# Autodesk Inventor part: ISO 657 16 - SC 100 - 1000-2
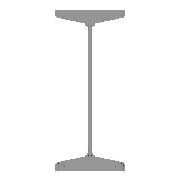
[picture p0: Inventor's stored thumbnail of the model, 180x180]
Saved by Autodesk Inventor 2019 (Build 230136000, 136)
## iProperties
_CCFamilyMember: 1
_CCFamilyDisplayName: ISO 657/16 - 1980 - Poutres en acier laminées à chaud - Partie 16: profilés en H (série métrique) - Cotes et propriétés de section
_FrameMemberDoc: Frame Member File
_Version: 15.0.0
_GetPNFromCC: 1
Created: 2018-07
Part Number: ISO 657 16 - SC 100 - 1000-2
Material: Acier, doux
Description: Poutres en acier laminées à chaud - Partie 16: profilés en H (série métrique) - Cotes et propriétés de section
Document SubType Name: Modeling
Standard: ISO
Designer: Fabian Perrée
Standard Revision: First edition 1980-02-15
Standards Organization: ISO
Language: fr-FR
Size Designation: SC 100
Categories: <MemberInstance><Categories><Category DisplayName="Profilés" InternalName="089c4875-fa83-4c05-b084-43b9cc11f5ed" Mnemonic="GRDR"><CategoryParameter DisplayName=
Stock Number: SC 100
Density: 7.85 g/cm^3
Appearance: Semi-poli
Mass: 19656.9 g
Surface Area: 5357.79 cm^2
Volume: 2504.06 cm^3
IsCustomPart: 1
G_W: 100,000 mm
G_H: 100,000 mm
+66B73B83-1ABF-4F18-8224-AF9602477DE0+DETAILDECOUPE1: Grugeage
+9F30C4B5-7857-4BA6-ACFD-6D0F8F96A7E8+DETAILDECOUPE2: Grugeage
G_L: 1000,000 mm
Author: Fabian Perrée
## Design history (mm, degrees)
node "Plan de départ"
node "Plan de fin"
sketch "Esquisse"
  geometry: L1 (-3, 0)-(-3, -26.266); L2 (-13.33, -38.149)-(-44.835, -42.577); L3 (-50, -48.518)-(-50, -50); L4 (-50, -50)-(0, -50); L5 (-26.5, -50)-(-26.5, -40); L6 (-61.333, 0)-(81.777, 0); L7 (0, 0)-(0, -50); L8 (0, -60)-(0, 80); L9 (3, 0)-(3, -26.266); L10 (13.33, -38.149)-(44.835, -42.577); L11 (50, -48.518)-(50, -50); L12 (50, -50)-(0, -50); L13 (-3, 0)-(0, 0); L14 (-3, 0)-(-3, 26.266); L15 (-13.33, 38.149)-(-44.835, 42.577); L16 (-50, 48.518)-(-50, 50); L17 (-50, 50)-(0, 50); L18 (50, 48.518)-(50, 50); L19 (13.33, 38.149)-(44.835, 42.577); L20 (3, 0)-(3, 26.266); L21 (50, 50)-(0, 50); L22 (0, 108)-(0, -88) reference; L23 (-89.955, 0)-(110.399, 0) reference; A1 r 6 centre (-44, 48.518) between (-50, 48.518) and (-44.835, 42.577); A2 r 6 centre (44, 48.518) between (44.835, 42.577) and (50, 48.518); A3 r 6 centre (44, -48.518) between (50, -48.518) and (44.835, -42.577); A4 r 6 centre (-44, -48.518) between (-44.835, -42.577) and (-50, -48.518); A5 r 12 centre (-15, 26.266) between (-3, 26.266) and (-13.33, 38.149); A6 r 12 centre (15, 26.266) between (13.33, 38.149) and (3, 26.266); A7 r 12 centre (15, -26.266) between (3, -26.266) and (13.33, -38.149); A8 r 12 centre (-15, -26.266) between (-13.33, -38.149) and (-3, -26.266); 14 further points
  constraints: 42 end point, 24 point on line, 17 symmetric about line, 16 point on circle, 16 tangent, 8 centre point, 6 equal radius, 4 collinear, 2 perpendicular, 12 other
  dimensions: "d1" = 10 vertical distance of L3.end L5.end (= G_T1); "d2" = 23.5 distance between parallel lines of L5 L3 (= -0.25 x G_T + 0.25 x G_W); "d3" = 3 distance between parallel lines of L1 L7 (= 0.5 x G_T); "d4" = 50 distance between parallel lines of L7 L3 (= 0.5 x G_W); "d9" = 50 distance from line of L1.start L4 (= 0.5 x G_H); "d14" = 98 deg angle of L2 L1 (= G_NG); "d15" = 6 radius of A1 (= G_ER); "d16" = 12 radius of A5 (= G_IR)
extrude "Corps" new body sketch "Esquisse" stored distance "d5" = 1000 (= G_L); taper "d6" = 0 deg
node "Driven Length"
  sketch "Sketch3"
    geometry: L1 (0, 0)-(10, 0) reference
    constraints: 2 end point, 1 horizontal
  workplane "Work Plane3"
  sketch "Sketch4"
    geometry: L1 (-2, 0)-(12, 0) reference; L2 (-2, 1000)-(12, 1000) reference
    dimensions: "d20" = 1000 distance between parallel lines of L1 L2 (derived)
node "Plan de construction4"
node "Plan de construction5"
node "Plan de construction6"
sketch "Esquisse5"
  geometry: L1 (-3, 0)-(-3, -26.266); L2 (-13.33, -38.149)-(-44.835, -42.577); L3 (-50, -48.518)-(-50, -50); L4 (-50, -50)-(0, -50); L5 (50, -50)-(0, -50); L6 (50, -48.518)-(50, -50); L7 (13.33, -38.149)-(44.835, -42.577); L8 (3, 0)-(3, -26.266); L9 (3, 0)-(3, 26.266); L10 (13.33, 38.149)-(44.835, 42.577); L11 (50, 48.518)-(50, 50); L12 (50, 50)-(0, 50); L13 (-50, 50)-(0, 50); L14 (-50, 48.518)-(-50, 50); L15 (-13.33, 38.149)-(-44.835, 42.577); L16 (-3, 0)-(-3, 26.266); A1 r 12 centre (-15, -26.266) between (-13.33, -38.149) and (-3, -26.266); A2 r 6 centre (-44, -48.518) between (-44.835, -42.577) and (-50, -48.518); A3 r 6 centre (44, -48.518) between (50, -48.518) and (44.835, -42.577); A4 r 12 centre (15, -26.266) between (3, -26.266) and (13.33, -38.149); A5 r 12 centre (15, 26.266) between (13.33, 38.149) and (3, 26.266); A6 r 6 centre (44, 48.518) between (44.835, 42.577) and (50, 48.518); A7 r 6 centre (-44, 48.518) between (-50, 48.518) and (-44.835, 42.577); A8 r 12 centre (-15, 26.266) between (-3, 26.266) and (-13.33, 38.149)
  constraints: 32 end point, 16 point on circle, 8 centre point
extrude "Extrusion2" cut sketch "Esquisse5" stored distance "d21" = 0.13; taper "d22" = 0 deg
node "Plan de construction7"
node "Plan de construction8"
node "Plan de construction9"
sketch "Esquisse6"
  geometry: L1 (-3, 0)-(-3, -26.266); L2 (-13.33, -38.149)-(-44.835, -42.577); L3 (-50, -48.518)-(-50, -50); L4 (-50, -50)-(0, -50); L5 (50, -50)-(0, -50); L6 (50, -48.518)-(50, -50); L7 (13.33, -38.149)-(44.835, -42.577); L8 (3, 0)-(3, -26.266); L9 (3, 0)-(3, 26.266); L10 (13.33, 38.149)-(44.835, 42.577); L11 (50, 48.518)-(50, 50); L12 (50, 50)-(0, 50); L13 (-50, 50)-(0, 50); L14 (-50, 48.518)-(-50, 50); L15 (-13.33, 38.149)-(-44.835, 42.577); L16 (-3, 0)-(-3, 26.266); A1 r 12 centre (-15, -26.266) between (-13.33, -38.149) and (-3, -26.266); A2 r 6 centre (-44, -48.518) between (-44.835, -42.577) and (-50, -48.518); A3 r 6 centre (44, -48.518) between (50, -48.518) and (44.835, -42.577); A4 r 12 centre (15, -26.266) between (3, -26.266) and (13.33, -38.149); A5 r 12 centre (15, 26.266) between (13.33, 38.149) and (3, 26.266); A6 r 6 centre (44, 48.518) between (44.835, 42.577) and (50, 48.518); A7 r 6 centre (-44, 48.518) between (-50, 48.518) and (-44.835, 42.577); A8 r 12 centre (-15, 26.266) between (-3, 26.266) and (-13.33, 38.149)
  constraints: 32 end point, 16 point on circle, 8 centre point
extrude "Extrusion3" cut sketch "Esquisse6" stored distance "d23" = 0.13; taper "d24" = 0 deg
body "Solid1"
other parameters: "G_W" = 100 (= G_H) [user parameter; used in 2 equation terms], "G_H" = 100 [user parameter; used in 2 equation terms], "G_T" = 6 [user parameter; used in 2 equation terms], "G_T1" = 10 [user parameter; used in 1 equation term], "G_L" = 1000 (= d20) [user parameter; used in 1 equation term], "G_ER" = 6 [user parameter; used in 1 equation term], "G_IR" = 12 [user parameter; used in 1 equation term], "G_NG" = 98 deg [user parameter; used in 1 equation term], "G_OFFSET_START" = 0 [user parameter; used in 1 equation term], "G_OFFSET_END" = 0 [user parameter; used in 1 equation term], "d17" = 0 (computed from G_OFFSET_START), "d19" = 90 deg
